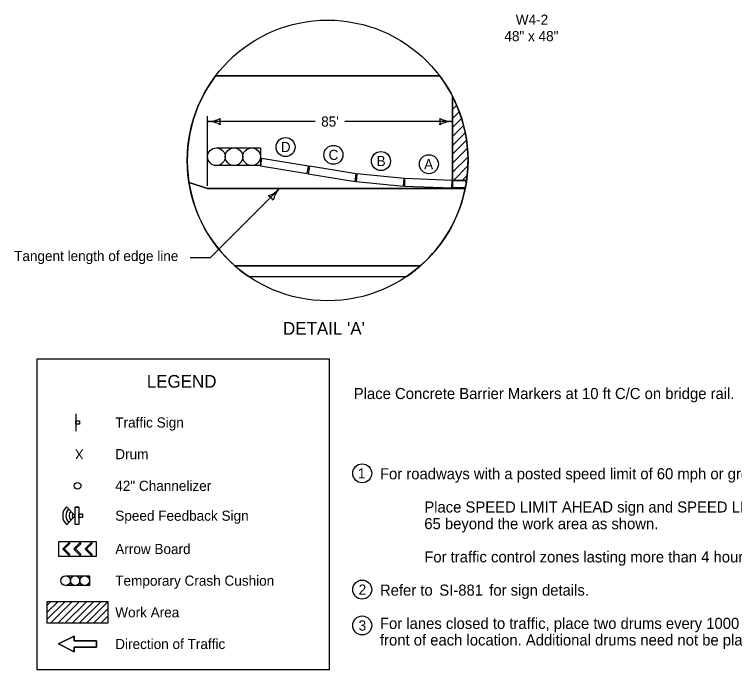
# Model space of a CAD drawing. Extents: x 10124 to 16850, y 7924 to 12166.
# Drawn here: x 10161 to 11298, y 7969 to 9003 of the extents above; entities that cross this region are included whole.
import ezdxf

# ---------------------------------------------------------------- set-up
doc = ezdxf.new("R2010")
doc.units = 0
for name, color, linetype in [('dsnShtPlotShapeBatchPrint', 7, 'Continuous'), ('dsnStdBorder', 7, 'Continuous'), ('dsnStdLabel', 7, 'Continuous'), ('dsnStdLineWork', 7, 'Continuous'), ('dsnStdShading', 7, 'Continuous'), ('Level 2', 7, 'Continuous'), ('SheetText', 7, 'Continuous')]:
    doc.layers.add(name, color=color, linetype=linetype)

msp = doc.modelspace()

# ---------------------------------------------------------------- linework, layer by layer
at = {"layer": 'dsnShtPlotShapeBatchPrint'}
for centre in [(10589.2, 8793.9), (10664.7, 8781.6), (10739.8, 8771.8), (10815.4, 8766.8), (10710.2, 8278.6), (10710.2, 8095), (10710.2, 8038.3)]:
    msp.add_circle(centre, 15, dxfattribs=at)
at = {"layer": 'dsnStdBorder'}
msp.add_line((10852.8, 8745.9), (10852.8, 8842.9), dxfattribs=at)
at = {"layer": 'dsnStdLabel'}
for p, q in [((10258.2, 8372.5), (10258.2, 8345)), ((10262.9, 8225.4), (10262.9, 8197.9)), ((10238.1, 8159.8), (10246.9, 8168.6)), ((10255.6, 8159.8), (10264.4, 8168.6)), ((10273.3, 8159.8), (10282.1, 8168.6)), ((10242.1, 8116.6), (10279.6, 8116.6)), ((10279.6, 8116.6), (10279.6, 8101.6)), ((10279.6, 8101.6), (10242.1, 8101.6)), ((10212.6, 8070.1), (10218.2, 8075.7)), ((10212.6, 8058.8), (10229.5, 8075.7)), ((10212.6, 8047.5), (10240.8, 8075.7)), ((10218.9, 8042.4), (10252.1, 8075.7)), ((10230.2, 8042.4), (10263.4, 8075.7)), ((10241.5, 8042.4), (10274.8, 8075.7)), ((10252.8, 8042.4), (10286.1, 8075.7)), ((10264.1, 8042.4), (10297.4, 8075.7)), ((10275.4, 8042.4), (10308.7, 8075.7)), ((10286.7, 8042.4), (10309.2, 8064.9)), ((10298, 8042.4), (10309.2, 8053.6))]:
    msp.add_line(p, q, dxfattribs=at)
for points in [[(10258.3, 8356), (10258.3, 8361.7), (10263.9, 8361.7), (10263.9, 8356)], [(10257.3, 8197.9), (10257.3, 8225.4), (10262.9, 8225.4), (10262.9, 8197.9)], [(10262.9, 8209), (10262.9, 8214.6), (10268.6, 8214.6), (10268.6, 8209)], [(10290.9, 8170.6), (10230.9, 8170.6), (10230.9, 8147.6), (10290.9, 8147.6)], [(10212.6, 8075.7), (10212.6, 8042.4), (10309.2, 8042.4), (10309.2, 8075.7)], [(10290.6, 8014.1), (10290.6, 8004.1), (10255.6, 8004.1), (10255.6, 7996.6), (10230.6, 8009.1), (10255.6, 8021.6), (10255.6, 8014.1)]]:
    msp.add_lwpolyline(points, close=True, dxfattribs=at)
for points in [[(10248.4, 8167.2), (10248.3, 8167.1), (10239.8, 8159.1), (10248.3, 8151)], [(10265.9, 8167.2), (10265.9, 8167.1), (10257.4, 8159.1), (10265.9, 8151)], [(10283.5, 8167.2), (10283.5, 8167.1), (10275, 8159.1), (10283.5, 8151)], [(10246.9, 8149.5), (10246.9, 8149.6), (10238.1, 8158.4), (10238.1, 8158.4)], [(10264.5, 8149.5), (10264.4, 8149.6), (10255.6, 8158.4), (10255.6, 8158.4)], [(10282.1, 8149.5), (10282.1, 8149.6), (10273.3, 8158.4), (10273.3, 8158.4)], [(10255.6, 8014.1), (10255.6, 8021.6), (10230.6, 8009.1), (10255.6, 7996.6), (10255.6, 8004.1), (10290.6, 8004.1), (10290.6, 8014.1), (10255.6, 8014.1)]]:
    msp.add_lwpolyline(points, dxfattribs=at)
for centre, radius in [((10480, 8778.6), 13.9), ((10507.8, 8778.6), 13.9), ((10535.6, 8778.6), 13.9), ((10260.9, 8258.9), 5.37), ((10260.9, 8258.9), 5.37), ((10242.1, 8109.1), 7.5), ((10242.1, 8109.1), 7.5), ((10257.1, 8109.1), 7.5), ((10257.1, 8109.1), 7.5), ((10272.1, 8109.1), 7.5), ((10272.1, 8109.1), 7.5)]:
    msp.add_circle(centre, radius, dxfattribs=at)
for centre, start, end in [((10247.6, 8167.9), 315.0975, 135.281), ((10265.2, 8167.9), 315.0975, 135.281), ((10282.8, 8167.9), 315.0975, 135.281), ((10238.8, 8159.1), 134.1616, 224.6098), ((10247.6, 8150.3), 226.201, 47.3602), ((10256.3, 8159.1), 134.1616, 224.6098), ((10265.2, 8150.3), 226.201, 47.3602), ((10274, 8159.1), 134.1616, 224.6098), ((10282.8, 8150.3), 226.201, 47.3602)]:
    msp.add_arc(centre, 1.03, start, end, dxfattribs=at)
at = {"layer": 'dsnStdLineWork'}
for p, q in [((10478.7, 8906.1), (10832.6, 8906.1)), ((10852.8, 8741.3), (10852.8, 8873.8)), ((10852.8, 8867.3), (10855, 8869.5)), ((10852.8, 8853.2), (10859.4, 8859.8)), ((10852.8, 8839.1), (10863.4, 8849.7)), ((10852.8, 8824.9), (10867, 8839.1)), ((10852.8, 8810.8), (10870.2, 8828.1)), ((10852.8, 8796.6), (10872.8, 8816.6)), ((10852.8, 8782.5), (10874.9, 8804.6)), ((10852.8, 8768.3), (10876.4, 8791.9)), ((10852.8, 8754.2), (10877.2, 8778.5)), ((10854.1, 8741.3), (10877.1, 8764.3)), ((10868.2, 8741.3), (10876, 8749.1)), ((10436.8, 8737.8), (10466.1, 8728.3)), ((10466.1, 8728.3), (10872.7, 8728.3)), ((10509.1, 8606.5), (10802.2, 8606.5))]:
    msp.add_line(p, q, dxfattribs=at)
for points in [[(10625.4, 8763.9), (10551.4, 8776), (10549.4, 8764.1), (10623.5, 8752)], [(10700.9, 8751.5), (10626.9, 8763.6), (10624.9, 8751.8), (10698.9, 8739.6)], [(10776.3, 8744.3), (10701.6, 8751.4), (10700.5, 8739.4), (10775.2, 8732.3)], [(10852.1, 8741.3), (10777.1, 8744.3), (10776.7, 8732.3), (10851.6, 8729.3)]]:
    msp.add_lwpolyline(points, close=True, dxfattribs=at)
for points in [[(10872.9, 8729.3), (10852.8, 8729.3), (10852.8, 8741.3), (10875, 8741.3)], [(10196.8, 8458.9), (10196.8, 7968.6), (10658.7, 7968.6), (10658.7, 8458.9), (10196.8, 8458.9)]]:
    msp.add_lwpolyline(points, dxfattribs=at)
at = {"layer": 'dsnStdShading'}
for p, q in [((10832.6, 8906.1), (10478.7, 8906.1)), ((10436.8, 8737.8), (10466.1, 8728.3)), ((10466.1, 8728.3), (10436.8, 8737.8)), ((10852.8, 8741.3), (10875, 8741.3)), ((10466.1, 8728.3), (10872.7, 8728.3)), ((10872.7, 8728.3), (10466.1, 8728.3)), ((10509.1, 8606.5), (10802.2, 8606.5)), ((10802.2, 8606.5), (10509.1, 8606.5)), ((10531.4, 8589.2), (10779.9, 8589.2))]:
    msp.add_line(p, q, dxfattribs=at)
for points in [[(10852.8, 8873.8), (10852.8, 8834.2), (10852.8, 8741.3)], [(10625.4, 8763.9), (10551.4, 8776), (10549.4, 8764.1), (10623.5, 8752), (10625.4, 8763.9)], [(10700.9, 8751.5), (10626.9, 8763.6), (10624.9, 8751.8), (10698.9, 8739.6), (10700.9, 8751.5)], [(10776.3, 8744.3), (10701.6, 8751.4), (10700.5, 8739.4), (10775.2, 8732.3), (10776.3, 8744.3)], [(10852.1, 8741.3), (10777.1, 8744.3), (10776.7, 8732.3), (10851.6, 8729.3), (10852.1, 8741.3)], [(10875, 8741.3), (10852.8, 8741.3), (10852.8, 8729.3), (10872.9, 8729.3)], [(10872.9, 8729.3), (10852.8, 8729.3), (10852.8, 8741.3), (10875, 8741.3)]]:
    msp.add_lwpolyline(points, dxfattribs=at)
for start, end in [(142.9773, 189.0659), (351.8621, 37.0227), (351.8621, 27.1505), (189.0659, 228.5906), (348.7138, 351.8621), (311.4094, 348.45), (348.45, 348.7138), (228.5906, 235.889), (304.111, 311.4094)]:
    msp.add_arc((10655.6, 8772.7), 221.6, start, end, dxfattribs=at)
at = {"layer": 'Level 2'}
for p, q in [((10480, 8792.5), (10549.4, 8792.5)), ((10549.4, 8792.5), (10549.4, 8764.7)), ((10549.4, 8764.7), (10480, 8764.7)), ((10548.8, 8763.5), (10548.8, 8763.5)), ((10243.2, 8225.8), (10257.3, 8211.7)), ((10262.9, 8225.4), (10257.3, 8225.4)), ((10257.3, 8211.7), (10243.2, 8197.5)), ((10262.9, 8197.9), (10257.3, 8197.9))]:
    msp.add_line(p, q, dxfattribs=at)
for centre in [(10480, 8778.6), (10480, 8778.6), (10507.8, 8778.6), (10507.8, 8778.6), (10535.6, 8778.6), (10535.6, 8778.6)]:
    msp.add_circle(centre, 13.9, dxfattribs=at)
for radius, start, end in [(20.3, 135.88, 224.0313), (15.3, 136.1665, 223.7159), (10.3, 136.7294, 223.0963), (5.32, 138.7005, 221.2995)]:
    msp.add_arc((10257.8, 8211.7), radius, start, end, dxfattribs=at)
at = {"layer": 'SheetText'}
for p, q in [((10466.1, 8732.9), (10466.1, 8842.9)), ((10636.1, 8834.2), (10466.1, 8834.2)), ((10852.8, 8834.2), (10682.8, 8834.2)), ((10852.8, 8745.9), (10852.8, 8842.9)), ((10579.4, 8728.3), (10470.6, 8619.7)), ((10438.6, 8619.7), (10470.6, 8619.7))]:
    msp.add_line(p, q, dxfattribs=at)
msp.add_circle((10655.6, 8772.7), 221.6, dxfattribs=at)
for centre, radius, start, end in [((10466.1, 8876.7), 42.5, 270, 298.0725), ((10466.1, 8791.7), 42.5, 61.9275, 90), ((10501.7, 8834.2), 16.4, 162.2666, 197.7334), ((10817.2, 8834.2), 16.4, 342.2666, 17.7334), ((10852.8, 8876.7), 42.5, 241.9275, 270), ((10852.8, 8791.7), 42.5, 90, 118.0725), ((10547.5, 8756.5), 42.5, 290.4723, 318.5448), ((10611.2, 8700.2), 42.5, 138.5448, 166.6173), ((10555.7, 8701.6), 16.4, 30.8115, 66.2782)]:
    msp.add_arc(centre, radius, start, end, dxfattribs=at)

# ---------------------------------------------------------------- texts
at = {"layer": 'dsnShtPlotShapeBatchPrint'}
for s, height, p in [('D', 16, (10581.7, 8785.9)), ('C', 16, (10657.1, 8773.6)), ('B', 16, (10732.9, 8763.8)), ('A', 16, (10807.9, 8758.8)), ('Place Concrete Barrier Markers at 10 ft C/C on bridge rail.', 17.5, (10696.9, 8395.9)), ('1', 16, (10703.3, 8270.6)), ('2', 16, (10704.6, 8087)), ('3', 16, (10704.5, 8030.3))]:
    msp.add_text(s, height=height, dxfattribs=at).set_placement(p)
at = {"layer": 'dsnStdLabel'}
for s, height, p in [("DETAIL 'A'", 20, (10585.2, 8497.5)), ('LEGEND', 20, (10370.2, 8413.9)), ('Traffic Sign', 16, (10320.4, 8350.9)), ('Drum', 16, (10320.4, 8300.9)), ('42" Channelizer ', 16, (10320.4, 8250.9)), ('Speed Feedback Sign', 16, (10320.4, 8203.7)), ('Arrow Board', 16, (10320.4, 8151.1)), ('Temporary Crash Cushion', 16, (10320.4, 8101.1)), ('Work Area', 16, (10320.4, 8051.1)), ('Direction of Traffic', 16, (10320.4, 8001.1))]:
    msp.add_text(s, height=height, dxfattribs=at).set_placement(p)
msp.add_text('X', height=15, rotation=180, dxfattribs=at).set_placement((10270.3, 8316.4))
at = {"layer": 'SheetText'}
for s, height, p in [('W4-2', 16, (10952.6, 8987.1)), ('48" x 48"', 16, (10934.6, 8961.1)), ("85'", 16, (10645.4, 8826.2)), ('Tangent length of edge line', 16, (10160.7, 8613.9)), ('For roadways with a posted speed limit of 60 mph or greater before road work:', 17.5, (10738.2, 8269.2)), ('Place SPEED LIMIT AHEAD sign and SPEED LIMIT 55 sign prior to the lane closure as shown. Place SPEED LIMIT', 17.5, (10808.2, 8216.7)), ('65 beyond the work area as shown.', 17.5, (10808.2, 8190.4)), ('For traffic control zones lasting more than 4 hours, place a Speed Feedback Sign at the end of the merge taper.', 17.5, (10808.2, 8137.9)), ('Refer to ', 17.5, (10738.2, 8085.4)), ('SI-881 ', 17.5, (10831.9, 8085.4)), ('for sign details.', 17.5, (10910.7, 8085.4)), ('For lanes closed to traffic, place two drums every 1000 feet. For full depth excavations in a closed lane, place two drums in ', 17.5, (10738.2, 8032.9)), ('front of each location. Additional drums need not be placed for full depth excavations spaced closer than 150 feet.', 17.5, (10738.2, 8006.7))]:
    msp.add_text(s, height=height, dxfattribs=at).set_placement(p)

doc.saveas('drawing.dxf')
